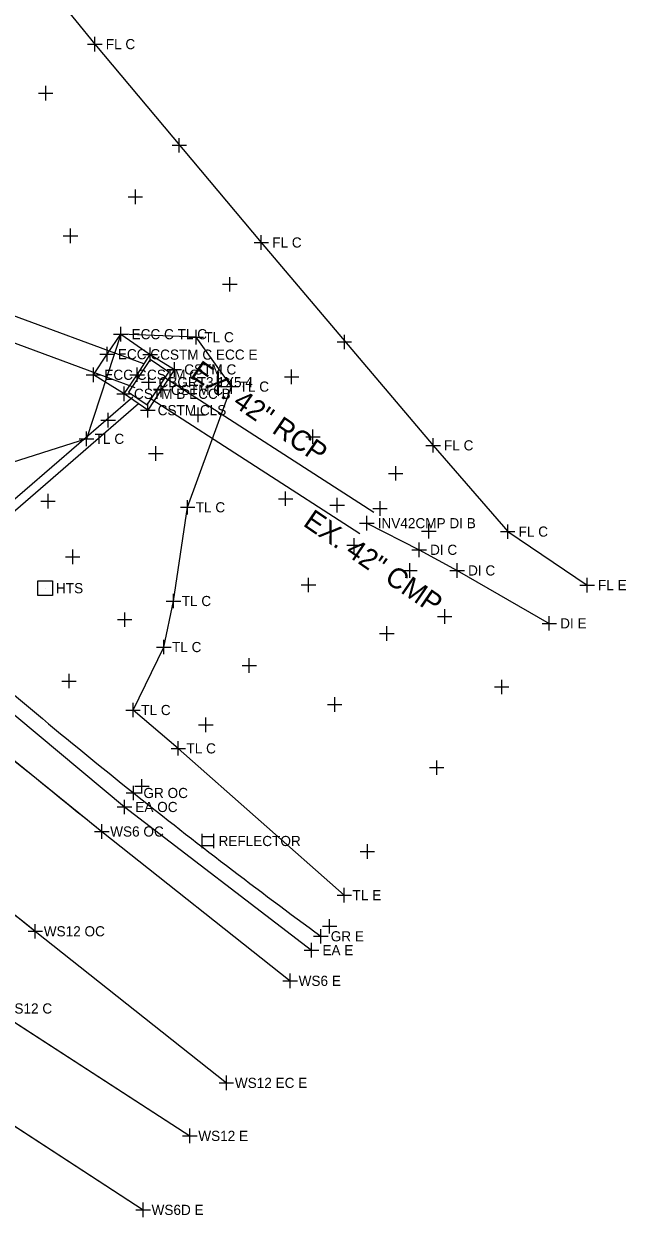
# Model space of a CAD drawing. Extents: x 1324236 to 1326110, y 459090 to 460782.
# Drawn here: x 1326027.3 to 1326110.3, y 459486 to 459650.5 of the extents above; entities that cross this region are included whole.
import ezdxf

# ---------------------------------------------------------------- set-up
doc = ezdxf.new("R2010")
doc.units = 0
for name, color, linetype in [('BD_X_Canopy', 7, 'Continuous'), ('DR_X_Ditch', 7, 'Continuous'), ('DR_X_Drive_Pipe', 7, 'Continuous'), ('DR_X_Paved_Gutter', 7, 'Continuous'), ('DT_X_Contour_Major', 7, 'Continuous'), ('DT_X_Terrain_Ground_Line', 7, 'Continuous'), ('DV_X_Property_Line', 7, 'Continuous'), ('LT_X_Poles', 7, 'Continuous'), ('PM_X_CL_Double_Solid', 7, 'Continuous'), ('PM_X_Edge_Line', 7, 'Continuous'), ('PM_X_Lane_Line', 7, 'Continuous'), ('PM_X_Parking_Lot_Stall', 7, 'Continuous'), ('PV_X_Shoulder', 7, 'Continuous'), ('RD_X_GR_Lt', 7, 'Continuous'), ('RW_X_CL', 7, 'Continuous'), ('RW_X_Esmt_SH', 7, 'Continuous'), ('UT_X_Electric', 7, 'Continuous'), ('UT_X_Telecom', 7, 'Continuous'), ('VG_X_Flower_Bed', 7, 'Continuous')]:
    doc.layers.add(name, color=color, linetype=linetype)

msp = doc.modelspace()

# ---------------------------------------------------------------- linework, layer by layer
at = {"layer": 'BD_X_Canopy'}
msp.add_lwpolyline([(1325729.36, 459692.27), (1325817.9, 459634.46), (1325908.1, 459575.52), (1325982.49, 459526.91), (1326043.74, 459486.99)], dxfattribs=at)
at = {"layer": 'DR_X_Ditch'}
for points in [[(1325894.93, 459661.79), (1325910.38, 459647.75), (1325910.38, 459647.75), (1325925.26, 459634.33), (1325925.26, 459634.33), (1325935.02, 459625.6), (1325935.02, 459625.6), (1325945.3, 459616.54), (1325945.3, 459616.54), (1325958.74, 459604.86), (1325958.74, 459604.86), (1325972.97, 459592.68), (1325972.97, 459592.68), (1325984.11, 459583.31), (1325984.11, 459583.31), (1325984.64, 459582.87), (1325984.64, 459582.87), (1326010.86, 459561.25), (1326010.86, 459561.25), (1326020.01, 459553.76), (1326020.01, 459553.76), (1326038.04, 459539.16), (1326038.04, 459539.16), (1326064, 459518.57)], [(1325929.76, 459608.19), (1325944.22, 459595.51), (1325944.22, 459595.51), (1325950.91, 459589.8), (1325950.91, 459589.8), (1325975.63, 459569.12), (1325975.63, 459569.12), (1325976.6, 459568.3), (1325976.6, 459568.3), (1325977.46, 459567.59), (1325977.46, 459567.59), (1326003.07, 459546.28), (1326011.53, 459539.33), (1326011.53, 459539.33), (1326028.87, 459525.4), (1326028.87, 459525.4), (1326055.21, 459504.5)], [(1325914.36, 459585.21), (1325938.12, 459569.86), (1325964.32, 459552.85), (1325994.05, 459533.56), (1326023.07, 459514.76), (1326050.18, 459497.19)]]:
    msp.add_lwpolyline(points, dxfattribs=at)
at = {"layer": 'DR_X_Drive_Pipe'}
for p, q in [((1326074.57, 459581.67), (1326081.79, 459578)), ((1326081.79, 459578), (1326087.03, 459575.15)), ((1326087.03, 459575.15), (1326099.72, 459567.86))]:
    msp.add_line(p, q, dxfattribs=at)
at = {"layer": 'DR_X_Paved_Gutter'}
for p, q in [((1326038.76, 459604.97), (1326040.65, 459607.73)), ((1326040.65, 459607.73), (1326044.72, 459604.91)), ((1326036.89, 459602.13), (1326038.76, 459604.97)), ((1326041.12, 459599.51), (1326036.89, 459602.13))]:
    msp.add_line(p, q, dxfattribs=at)
msp.add_lwpolyline([(1326041.12, 459599.51), (1326036.89, 459602.13), (1326038.76, 459604.97), (1326040.65, 459607.73), (1326044.72, 459604.91)], dxfattribs=at)
at = {"layer": 'DT_X_Contour_Major'}
msp.add_line((1326030.23, 459572.71), (1326030.23, 459572.71), dxfattribs=at)
msp.add_lwpolyline([(1326029.23, 459571.71), (1326029.23, 459573.71), (1326031.23, 459573.71), (1326031.23, 459571.71), (1326029.23, 459571.71)], dxfattribs=at)
at = {"layer": 'DT_X_Terrain_Ground_Line'}
for p, q in [((1326051.83, 459538.85), (1326051.83, 459536.85)), ((1326051.83, 459538.45), (1326053.43, 459538.45)), ((1326053.43, 459538.85), (1326053.43, 459536.85)), ((1326051.83, 459537.24), (1326053.43, 459537.24))]:
    msp.add_line(p, q, dxfattribs=at)
at = {"layer": 'DV_X_Property_Line'}
for p, q in [((1326039.65, 459607.73), (1326041.65, 459607.73)), ((1326040.65, 459606.73), (1326040.65, 459608.73)), ((1326038.76, 459603.97), (1326038.76, 459605.97)), ((1326044.72, 459603.91), (1326044.72, 459605.91)), ((1326037.76, 459604.97), (1326039.76, 459604.97)), ((1326043.72, 459604.91), (1326045.72, 459604.91)), ((1326036.89, 459601.13), (1326036.89, 459603.13)), ((1326042.91, 459601.14), (1326042.91, 459603.14)), ((1326047.04, 459602.87), (1326049.04, 459602.87)), ((1326048.04, 459601.87), (1326048.04, 459603.87)), ((1326035.89, 459602.13), (1326037.89, 459602.13)), ((1326041.91, 459602.14), (1326043.91, 459602.14)), ((1326046.22, 459599.05), (1326046.22, 459601.05)), ((1326040.12, 459599.51), (1326042.12, 459599.51)), ((1326041.12, 459598.51), (1326041.12, 459600.51)), ((1326045.22, 459600.05), (1326047.22, 459600.05)), ((1326044.39, 459596.25), (1326044.39, 459598.25)), ((1326043.39, 459597.25), (1326045.39, 459597.25)), ((1326073.57, 459581.67), (1326075.57, 459581.67)), ((1326074.57, 459580.67), (1326074.57, 459582.67)), ((1326041.16, 459541.54), (1326041.16, 459543.54)), ((1326040.16, 459542.54), (1326042.16, 459542.54)), ((1326066.95, 459521.8), (1326066.95, 459523.8)), ((1326065.95, 459522.8), (1326067.95, 459522.8))]:
    msp.add_line(p, q, dxfattribs=at)
at = {"layer": 'LT_X_Poles'}
for points in [[(1325894.93, 459661.79), (1325910.38, 459647.75), (1325910.38, 459647.75), (1325925.26, 459634.33), (1325925.26, 459634.33), (1325935.02, 459625.6), (1325935.02, 459625.6), (1325945.3, 459616.54), (1325945.3, 459616.54), (1325958.74, 459604.86), (1325958.74, 459604.86), (1325972.97, 459592.68), (1325972.97, 459592.68), (1325984.11, 459583.31), (1325984.11, 459583.31), (1325984.64, 459582.87), (1325984.64, 459582.87), (1326010.86, 459561.25), (1326010.86, 459561.25), (1326020.01, 459553.76), (1326020.01, 459553.76), (1326038.04, 459539.16), (1326038.04, 459539.16), (1326064, 459518.57)], [(1325929.76, 459608.19), (1325944.22, 459595.51), (1325944.22, 459595.51), (1325950.91, 459589.8), (1325950.91, 459589.8), (1325975.63, 459569.12), (1325975.63, 459569.12), (1325976.6, 459568.3), (1325976.6, 459568.3), (1325977.46, 459567.59), (1325977.46, 459567.59), (1326003.07, 459546.28), (1326011.53, 459539.33), (1326011.53, 459539.33), (1326028.87, 459525.4), (1326028.87, 459525.4), (1326055.21, 459504.5)], [(1325914.36, 459585.21), (1325938.12, 459569.86), (1325964.32, 459552.85), (1325994.05, 459533.56), (1326023.07, 459514.76), (1326050.18, 459497.19)]]:
    msp.add_lwpolyline(points, dxfattribs=at)
at = {"layer": 'PM_X_CL_Double_Solid'}
for p, q in [((1326021.14, 459667.36), (1326037.09, 459647.72)), ((1326037.09, 459647.72), (1326060.03, 459620.37)), ((1326060.03, 459620.37), (1326083.7, 459592.4)), ((1326083.7, 459592.4), (1326093.99, 459580.51)), ((1326093.99, 459580.51), (1326104.94, 459573.13))]:
    msp.add_line(p, q, dxfattribs=at)
at = {"layer": 'PM_X_Edge_Line'}
for p, q in [((1326038.04, 459539.16), (1326064, 459518.57)), ((1326028.87, 459525.4), (1326055.21, 459504.5)), ((1326023.07, 459514.76), (1326050.18, 459497.19))]:
    msp.add_line(p, q, dxfattribs=at)
for centre, radius, start, end in [((1330219.48, 464719.74), 6657.54, 230.892087, 231.091714), ((1328040.12, 462047.19), 3225.6, 231.0308, 231.42588)]:
    msp.add_arc(centre, radius, start, end, dxfattribs=at)
at = {"layer": 'PM_X_Lane_Line'}
msp.add_line((1325982.49, 459526.91), (1326043.74, 459486.99), dxfattribs=at)
at = {"layer": 'PM_X_Parking_Lot_Stall'}
for start, end in [(228.8633, 231.39317), (231.39317, 233.77207)]:
    msp.add_arc((1326531.09, 460156.47), 783.16, start, end, dxfattribs=at)
at = {"layer": 'PV_X_Shoulder'}
msp.add_lwpolyline([(1325913.97, 459651.72), (1325924.33, 459642.37), (1325924.33, 459642.37), (1325938.66, 459629.62), (1325938.66, 459629.62), (1325951.02, 459618.8), (1325951.02, 459618.8), (1325962.58, 459608.87), (1325962.58, 459608.87), (1325975.02, 459598.5), (1325975.02, 459598.5), (1325987.8, 459587.85), (1325987.8, 459587.85), (1325991.6, 459584.6), (1325991.6, 459584.6), (1326014.06, 459565.31), (1326014.06, 459565.31), (1326023.2, 459557.54), (1326023.2, 459557.54), (1326041.16, 459542.54), (1326041.16, 459542.54), (1326066.95, 459522.8)], dxfattribs=at)
at = {"layer": 'RD_X_GR_Lt'}
for p, q in [((1326040.65, 459607.73), (1326035.94, 459593.3)), ((1326051.06, 459607.31), (1326040.65, 459607.73)), ((1326055.91, 459600.5), (1326051.06, 459607.31)), ((1326049.87, 459583.86), (1326055.91, 459600.5)), ((1326035.94, 459593.3), (1326019.49, 459588.09)), ((1326047.93, 459570.94), (1326049.87, 459583.86)), ((1326046.59, 459564.59), (1326047.93, 459570.94)), ((1326042.35, 459555.91), (1326046.59, 459564.59)), ((1326048.58, 459550.62), (1326042.35, 459555.91)), ((1326071.47, 459530.38), (1326048.58, 459550.62))]:
    msp.add_line(p, q, dxfattribs=at)
at = {"layer": 'RW_X_CL'}
for p, q in [((1326029.31, 459640.96), (1326031.31, 459640.96)), ((1326030.31, 459639.96), (1326030.31, 459641.96)), ((1326048.72, 459632.77), (1326048.72, 459634.77)), ((1326047.72, 459633.77), (1326049.72, 459633.77)), ((1326042.67, 459625.67), (1326042.67, 459627.67)), ((1326041.67, 459626.67), (1326043.67, 459626.67)), ((1326032.73, 459621.28), (1326034.73, 459621.28)), ((1326033.73, 459620.28), (1326033.73, 459622.28)), ((1326054.68, 459614.61), (1326056.68, 459614.61)), ((1326055.68, 459613.61), (1326055.68, 459615.61)), ((1326071.48, 459605.66), (1326071.48, 459607.66)), ((1326070.48, 459606.66), (1326072.48, 459606.66)), ((1326064.21, 459600.85), (1326064.21, 459602.85)), ((1326043.51, 459601.11), (1326045.51, 459601.11)), ((1326044.51, 459600.11), (1326044.51, 459602.11)), ((1326063.21, 459601.85), (1326065.21, 459601.85)), ((1326038.93, 459594.87), (1326038.93, 459596.87)), ((1326050.33, 459596.61), (1326052.33, 459596.61)), ((1326051.33, 459595.61), (1326051.33, 459597.61)), ((1326037.93, 459595.87), (1326039.93, 459595.87)), ((1326067.15, 459592.59), (1326067.15, 459594.59)), ((1326066.15, 459593.59), (1326068.15, 459593.59)), ((1326044.5, 459591.27), (1326046.5, 459591.27)), ((1326045.5, 459590.27), (1326045.5, 459592.27)), ((1326078.55, 459587.54), (1326078.55, 459589.54)), ((1326077.55, 459588.54), (1326079.55, 459588.54)), ((1326029.63, 459584.7), (1326031.63, 459584.7)), ((1326030.63, 459583.7), (1326030.63, 459585.7)), ((1326062.38, 459585.04), (1326064.38, 459585.04)), ((1326063.38, 459584.04), (1326063.38, 459586.04)), ((1326070.49, 459583.15), (1326070.49, 459585.15)), ((1326076.39, 459582.7), (1326076.39, 459584.7)), ((1326069.49, 459584.15), (1326071.49, 459584.15)), ((1326075.39, 459583.7), (1326077.39, 459583.7)), ((1326083.13, 459579.57), (1326083.13, 459581.57)), ((1326072.84, 459577.62), (1326072.84, 459579.62)), ((1326082.13, 459580.57), (1326084.13, 459580.57)), ((1326034.03, 459576.04), (1326034.03, 459578.04)), ((1326071.84, 459578.62), (1326073.84, 459578.62)), ((1326033.03, 459577.04), (1326035.03, 459577.04)), ((1326079.51, 459575.14), (1326081.51, 459575.14)), ((1326080.51, 459574.14), (1326080.51, 459576.14)), ((1326065.53, 459573.15), (1326067.53, 459573.15)), ((1326066.53, 459572.15), (1326066.53, 459574.15)), ((1326085.31, 459567.8), (1326085.31, 459569.8)), ((1326040.2, 459568.37), (1326042.2, 459568.37)), ((1326041.2, 459567.37), (1326041.2, 459569.37)), ((1326084.31, 459568.8), (1326086.31, 459568.8)), ((1326076.32, 459566.47), (1326078.32, 459566.47)), ((1326077.32, 459565.47), (1326077.32, 459567.47)), ((1326057.37, 459562.05), (1326059.37, 459562.05)), ((1326058.37, 459561.05), (1326058.37, 459563.05)), ((1326032.53, 459559.9), (1326034.53, 459559.9)), ((1326033.53, 459558.9), (1326033.53, 459560.9)), ((1326093.16, 459558.09), (1326093.16, 459560.09)), ((1326092.16, 459559.09), (1326094.16, 459559.09)), ((1326069.15, 459556.66), (1326071.15, 459556.66)), ((1326070.15, 459555.66), (1326070.15, 459557.66)), ((1326052.39, 459552.87), (1326052.39, 459554.87)), ((1326051.39, 459553.87), (1326053.39, 459553.87)), ((1326084.21, 459546.97), (1326084.21, 459548.97)), ((1326083.21, 459547.97), (1326085.21, 459547.97)), ((1326042.58, 459545.39), (1326044.58, 459545.39)), ((1326043.58, 459544.39), (1326043.58, 459546.39)), ((1326038.04, 459538.16), (1326038.04, 459540.16)), ((1326037.04, 459539.16), (1326039.04, 459539.16)), ((1326074.65, 459535.4), (1326074.65, 459537.4)), ((1326073.65, 459536.4), (1326075.65, 459536.4)), ((1326069.44, 459525.09), (1326069.44, 459527.09)), ((1326027.87, 459525.4), (1326029.87, 459525.4)), ((1326028.87, 459524.4), (1326028.87, 459526.4)), ((1326068.44, 459526.09), (1326070.44, 459526.09)), ((1326064, 459517.57), (1326064, 459519.57)), ((1326063, 459518.57), (1326065, 459518.57)), ((1326055.21, 459503.5), (1326055.21, 459505.5)), ((1326054.21, 459504.5), (1326056.21, 459504.5)), ((1326050.18, 459496.19), (1326050.18, 459498.19)), ((1326049.18, 459497.19), (1326051.18, 459497.19)), ((1326043.74, 459485.99), (1326043.74, 459487.99)), ((1326042.74, 459486.99), (1326044.74, 459486.99))]:
    msp.add_line(p, q, dxfattribs=at)
at = {"layer": 'RW_X_Esmt_SH'}
for p, q in [((1326037.09, 459646.72), (1326037.09, 459648.72)), ((1326036.09, 459647.72), (1326038.09, 459647.72)), ((1326060.03, 459619.37), (1326060.03, 459621.37)), ((1326059.03, 459620.37), (1326061.03, 459620.37)), ((1326051.06, 459606.31), (1326051.06, 459608.31)), ((1326050.06, 459607.31), (1326052.06, 459607.31)), ((1326055.91, 459599.5), (1326055.91, 459601.5)), ((1326054.91, 459600.5), (1326056.91, 459600.5)), ((1326034.94, 459593.3), (1326036.94, 459593.3)), ((1326035.94, 459592.3), (1326035.94, 459594.3)), ((1326083.7, 459591.4), (1326083.7, 459593.4)), ((1326082.7, 459592.4), (1326084.71, 459592.4)), ((1326049.87, 459582.86), (1326049.87, 459584.86)), ((1326048.87, 459583.86), (1326050.87, 459583.86)), ((1326093.99, 459579.51), (1326093.99, 459581.51)), ((1326092.99, 459580.51), (1326094.99, 459580.51)), ((1326080.79, 459578), (1326082.79, 459578)), ((1326081.79, 459577), (1326081.79, 459579)), ((1326086.03, 459575.15), (1326088.03, 459575.15)), ((1326087.03, 459574.15), (1326087.03, 459576.15)), ((1326103.94, 459573.13), (1326105.94, 459573.13)), ((1326104.94, 459572.13), (1326104.94, 459574.13)), ((1326047.93, 459569.94), (1326047.93, 459571.94)), ((1326046.93, 459570.94), (1326048.93, 459570.94)), ((1326099.72, 459566.86), (1326099.72, 459568.86)), ((1326098.72, 459567.86), (1326100.72, 459567.86)), ((1326046.59, 459563.59), (1326046.59, 459565.59)), ((1326045.59, 459564.59), (1326047.59, 459564.59)), ((1326042.35, 459554.91), (1326042.35, 459556.91)), ((1326041.35, 459555.91), (1326043.35, 459555.91)), ((1326048.58, 459549.62), (1326048.58, 459551.62)), ((1326047.58, 459550.62), (1326049.58, 459550.62)), ((1326042.42, 459543.47), (1326042.42, 459545.47)), ((1326041.42, 459544.47), (1326043.42, 459544.47)), ((1326070.47, 459530.38), (1326072.47, 459530.38)), ((1326071.47, 459529.38), (1326071.47, 459531.38)), ((1326068.24, 459523.71), (1326068.24, 459525.71)), ((1326067.24, 459524.71), (1326069.24, 459524.71))]:
    msp.add_line(p, q, dxfattribs=at)
at = {"layer": 'UT_X_Electric'}
for p, q in [((1326042.91, 459602.14), (1326044.72, 459604.91)), ((1326044.72, 459604.91), (1326048.04, 459602.87)), ((1326048.04, 459602.87), (1326046.22, 459600.05)), ((1326041.12, 459599.51), (1326042.91, 459602.14)), ((1326044.39, 459597.25), (1326041.12, 459599.51)), ((1326046.22, 459600.05), (1326044.39, 459597.25))]:
    msp.add_line(p, q, dxfattribs=at)
msp.add_lwpolyline([(1326041.71, 459599.74), (1326044.28, 459598.01), (1326047.3, 459602.49), (1326044.73, 459604.22)], close=True, dxfattribs=at)
at = {"layer": 'VG_X_Flower_Bed'}
for p, q in [((1326043.83, 459603.62), (1325979.85, 459627.22)), ((1326042.62, 459600.34), (1325978.64, 459623.94)), ((1326075.52, 459583.14), (1326046.74, 459601.72)), ((1325937.97, 459509.03), (1326042.3, 459599.11)), ((1325938.79, 459508.08), (1326043.12, 459598.16)), ((1326073.63, 459580.2), (1326044.84, 459598.78))]:
    msp.add_line(p, q, dxfattribs=at)

# ---------------------------------------------------------------- texts
at = {"layer": 'DT_X_Contour_Major'}
msp.add_text('HTS', height=1.4, dxfattribs=at).set_placement((1326031.73, 459572.01))
at = {"layer": 'DV_X_Property_Line'}
for s, p in [('ECC C TL C', (1326042.15, 459607.03)), ('ECC C', (1326040.26, 459604.27)), ('CSTM C ECC E', (1326046.08, 459604.21)), ('ECC C', (1326038.39, 459601.43)), ('CSTM C', (1326044.27, 459601.44)), ('CSTM C', (1326049.4, 459602.17)), ('CSTM B ECC B', (1326042.48, 459598.81)), ('CSTM C', (1326047.58, 459599.35)), ('CSTM CLS', (1326045.74, 459596.55)), ('INV42CMP DI B', (1326076.07, 459580.97)), ('EA OC', (1326042.66, 459541.84)), ('EA E', (1326068.45, 459522.1))]:
    msp.add_text(s, height=1.4, dxfattribs=at).set_placement(p)
at = {"layer": 'RW_X_CL'}
for s, p in [('CBGRT3.1X5.4', (1326045.86, 459600.41)), ('WS6 OC', (1326039.2, 459538.46)), ('WS12 OC', (1326030.04, 459524.7)), ('WS6 E', (1326065.17, 459517.87)), ('WS12 C', (1326024.23, 459514.06)), ('WS12 EC E', (1326056.38, 459503.8)), ('WS12 E', (1326051.34, 459496.49)), ('WS6D E', (1326044.9, 459486.29))]:
    msp.add_text(s, height=1.4, dxfattribs=at).set_placement(p)
at = {"layer": 'RW_X_Esmt_SH'}
for s, p in [('FL C', (1326038.59, 459647.02)), ('FL C', (1326061.53, 459619.67)), ('TL C', (1326052.18, 459606.61)), ('TL C', (1326057.04, 459599.8)), ('TL C', (1326037.07, 459592.6)), ('FL C', (1326085.21, 459591.7)), ('TL C', (1326050.99, 459583.16)), ('FL C', (1326095.49, 459579.81)), ('DI C', (1326083.29, 459577.3)), ('DI C', (1326088.53, 459574.45)), ('FL E', (1326106.44, 459572.43)), ('TL C', (1326049.06, 459570.24)), ('DI E', (1326101.22, 459567.16)), ('TL C', (1326047.72, 459563.89)), ('TL C', (1326043.47, 459555.21)), ('TL C', (1326049.71, 459549.92)), ('GR OC', (1326043.78, 459543.77)), ('REFLECTOR', (1326054.13, 459537.15)), ('TL E', (1326072.6, 459529.68)), ('GR E', (1326069.6, 459524.01))]:
    msp.add_text(s, height=1.4, dxfattribs=at).set_placement(p)
at = {"layer": 'UT_X_Telecom'}
for s, p in [('EX. 42" RCP', (1326050.13, 459601.94)), ('EX. 42" CMP', (1326065.65, 459581.41))]:
    msp.add_text(s, height=2.8, rotation=325.5354, dxfattribs=at).set_placement(p)

doc.saveas('drawing.dxf')
